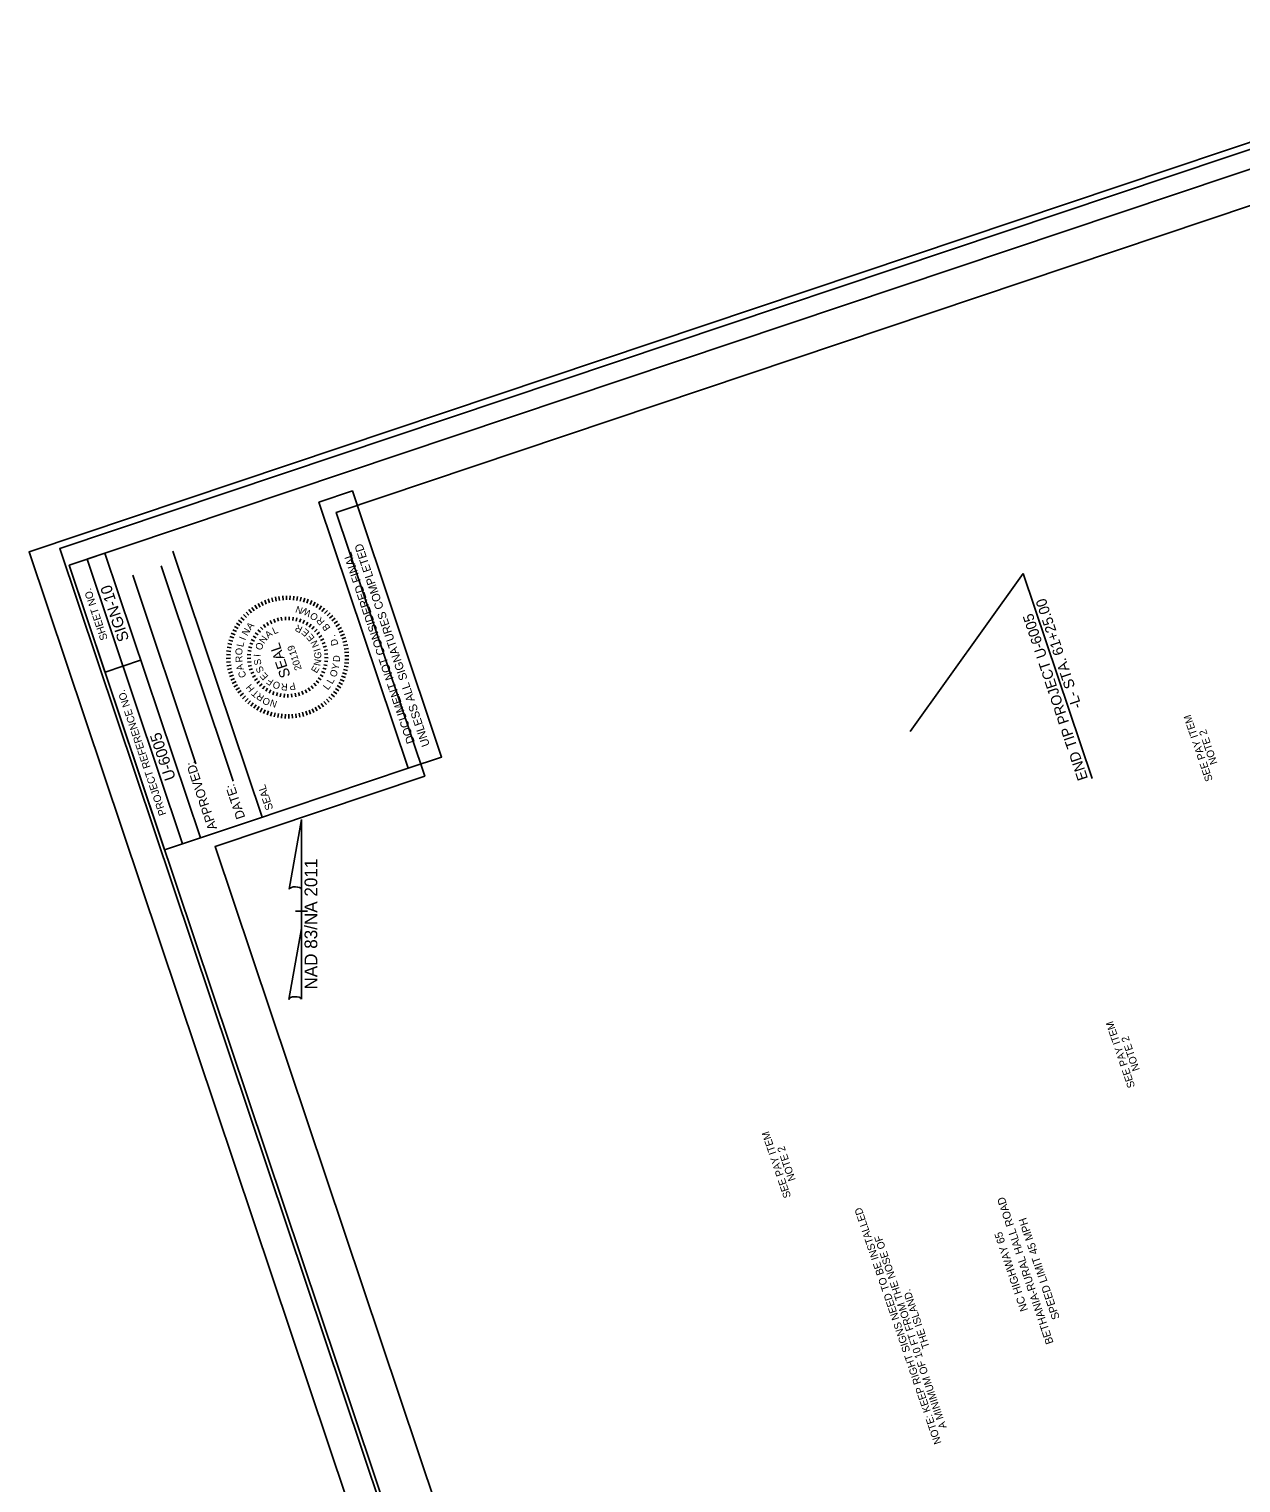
# Model space of a CAD drawing. Extents: x 1615436 to 1617010, y 903110 to 905055.
# Drawn here: x 1615436 to 1616244, y 904086 to 905055 of the extents above; entities that cross this region are included whole.
import ezdxf

# ---------------------------------------------------------------- set-up
doc = ezdxf.new("R2010")
doc.units = 0
for name, color, linetype in [('Default', 7, 'Continuous'), ('Exist DTM Regular Point Cogo Number', 7, 'Continuous'), ('Exist Structure Minor Pipes CMP 15 Inch Cogo Number', 7, 'Continuous'), ('Exist Structure Minor Pipes CMP 15 Inch Cogo Point CELL', 7, 'Continuous'), ('Exist Structure Minor Pipes RCP 15 Inch Cogo Number', 7, 'Continuous'), ('Exist Utilities Sanitary Sewer Manhole Cogo Number', 7, 'Continuous'), ('Prop RDY Traffic Signal CELL', 7, 'Continuous'), ('Sheet Layout Plan Border', 7, 'Continuous'), ('Sheet North Arrow Point CELL', 7, 'Continuous'), ('Sheet Plan CELL', 7, 'Continuous'), ('Sheet Plan Layout CELL', 7, 'Continuous'), ('Sheet Sticker Exception Certification CELL', 7, 'Continuous'), ('Sheet Sticker Preliminary CELL', 7, 'Continuous')]:
    doc.layers.add(name, color=color, linetype=linetype)

msp = doc.modelspace()

# ---------------------------------------------------------------- linework, layer by layer
at = {"layer": 'Default'}
for p, q in [((1615588.96, 904672.22), (1615590.31, 904669.78)), ((1615591.16, 904673.35), (1615592.35, 904670.83)), ((1615593.42, 904674.34), (1615594.46, 904671.76)), ((1615595.74, 904675.19), (1615596.62, 904672.55)), ((1615598.1, 904675.91), (1615598.83, 904673.22)), ((1615600.51, 904676.47), (1615601.07, 904673.75)), ((1615602.94, 904676.9), (1615603.33, 904674.14)), ((1615605.39, 904677.17), (1615605.62, 904674.39)), ((1615607.86, 904677.3), (1615607.92, 904674.51)), ((1615610.33, 904677.27), (1615610.21, 904674.49)), ((1615612.79, 904677.1), (1615612.51, 904674.33)), ((1615615.24, 904676.78), (1615614.79, 904674.03)), ((1615617.66, 904676.31), (1615617.05, 904673.59)), ((1615620.05, 904675.7), (1615619.28, 904673.02)), ((1615622.4, 904674.94), (1615621.47, 904672.31)), ((1615624.71, 904674.04), (1615623.61, 904671.48)), ((1615626.95, 904673), (1615625.7, 904670.51)), ((1615577.55, 904662.9), (1615579.68, 904661.09)), ((1615579.21, 904664.73), (1615581.22, 904662.8)), ((1615580.97, 904666.46), (1615582.86, 904664.41)), ((1615582.83, 904668.08), (1615584.6, 904665.92)), ((1615584.79, 904669.58), (1615586.42, 904667.32)), ((1615586.84, 904670.97), (1615588.32, 904668.61)), ((1615602.03, 904662.53), (1615602.61, 904660.28)), ((1615604.86, 904660.74), (1615604.49, 904663.04)), ((1615607.17, 904663.33), (1615607.3, 904661.01)), ((1615609.77, 904663.35), (1615609.68, 904661.03)), ((1615612.37, 904663.12), (1615612.05, 904660.82)), ((1615614.92, 904662.64), (1615614.39, 904660.38)), ((1615629.12, 904671.84), (1615627.73, 904669.42)), ((1615631.22, 904670.54), (1615629.69, 904668.22)), ((1615633.24, 904669.12), (1615631.57, 904666.89)), ((1615635.17, 904667.58), (1615633.37, 904665.45)), ((1615637, 904665.92), (1615635.07, 904663.91)), ((1615638.73, 904664.16), (1615636.68, 904662.27)), ((1615572.13, 904654.67), (1615574.62, 904653.43)), ((1615573.29, 904656.85), (1615575.7, 904655.46)), ((1615574.59, 904658.95), (1615576.91, 904657.41)), ((1615576.01, 904660.97), (1615578.24, 904659.3)), ((1615588.82, 904654.6), (1615590.53, 904653.04)), ((1615590.66, 904656.44), (1615592.22, 904654.72)), ((1615592.68, 904658.09), (1615594.06, 904656.22)), ((1615594.84, 904659.53), (1615596.04, 904657.54)), ((1615597.14, 904660.76), (1615598.13, 904658.67)), ((1615599.54, 904661.76), (1615600.33, 904659.58)), ((1615617.43, 904661.92), (1615616.68, 904659.72)), ((1615619.84, 904660.95), (1615618.89, 904658.84)), ((1615622.16, 904659.77), (1615621, 904657.75)), ((1615624.35, 904658.36), (1615623, 904656.47)), ((1615626.39, 904656.75), (1615624.87, 904654.99)), ((1615628.27, 904654.94), (1615626.58, 904653.35)), ((1615629.97, 904652.97), (1615628.13, 904651.54)), ((1615640.35, 904662.3), (1615638.19, 904660.53)), ((1615641.86, 904660.34), (1615639.59, 904658.71)), ((1615643.24, 904658.29), (1615640.88, 904656.8)), ((1615644.5, 904656.17), (1615642.06, 904654.82)), ((1615645.62, 904653.97), (1615643.11, 904652.78)), ((1615568.82, 904645.39), (1615571.54, 904644.78)), ((1615569.43, 904647.78), (1615572.11, 904647.01)), ((1615570.19, 904650.13), (1615572.81, 904649.2)), ((1615571.09, 904652.43), (1615573.65, 904651.34)), ((1615582.65, 904643.28), (1615584.9, 904642.69)), ((1615583.43, 904645.77), (1615585.61, 904644.96)), ((1615584.45, 904648.16), (1615586.54, 904647.15)), ((1615585.7, 904650.45), (1615587.68, 904649.24)), ((1615587.15, 904652.6), (1615589.02, 904651.21)), ((1615631.46, 904650.84), (1615629.5, 904649.59)), ((1615632.75, 904648.57), (1615630.68, 904647.53)), ((1615633.81, 904646.2), (1615631.64, 904645.36)), ((1615634.63, 904643.73), (1615632.4, 904643.1)), ((1615646.61, 904651.71), (1615644.03, 904650.67)), ((1615647.47, 904649.39), (1615644.82, 904648.51)), ((1615648.18, 904647.03), (1615645.49, 904646.3)), ((1615648.75, 904644.62), (1615646.02, 904644.06)), ((1615567.83, 904635.59), (1615570.62, 904635.65)), ((1615567.86, 904638.05), (1615570.64, 904637.94)), ((1615568.03, 904640.52), (1615570.8, 904640.24)), ((1615568.35, 904642.96), (1615571.1, 904642.52)), ((1615581.77, 904635.54), (1615584.1, 904635.62)), ((1615581.81, 904638.15), (1615584.13, 904638)), ((1615582.11, 904640.74), (1615584.4, 904640.37)), ((1615635.22, 904641.19), (1615632.93, 904640.78)), ((1615635.47, 904633.41), (1615633.16, 904633.67)), ((1615633.24, 904638.41), (1615635.56, 904638.59)), ((1615635.64, 904636.01), (1615633.31, 904636.05)), ((1615649.17, 904642.19), (1615646.41, 904641.8)), ((1615649.44, 904639.74), (1615646.67, 904639.51)), ((1615649.55, 904634.8), (1615646.76, 904634.92)), ((1615649.57, 904637.27), (1615646.78, 904637.21)), ((1615567.96, 904633.12), (1615570.74, 904633.35)), ((1615568.23, 904630.66), (1615570.99, 904631.06)), ((1615568.66, 904628.23), (1615571.38, 904628.79)), ((1615569.22, 904625.83), (1615571.91, 904626.55)), ((1615569.94, 904623.47), (1615572.58, 904624.35)), ((1615581.99, 904632.95), (1615584.29, 904633.25)), ((1615582.45, 904630.39), (1615584.71, 904630.91)), ((1615583.15, 904627.88), (1615585.35, 904628.62)), ((1615585.35, 904628.62), (1615583.15, 904627.88)), ((1615584.1, 904625.46), (1615586.22, 904626.4)), ((1615585.27, 904623.14), (1615587.29, 904624.28)), ((1615632.36, 904623.54), (1615630.32, 904624.65)), ((1615633.49, 904625.88), (1615631.35, 904626.79)), ((1615634.39, 904628.32), (1615632.18, 904629.02)), ((1615635.05, 904630.84), (1615632.78, 904631.32)), ((1615647.97, 904625.07), (1615645.29, 904625.85)), ((1615648.58, 904627.47), (1615645.86, 904628.08)), ((1615649.05, 904629.89), (1615646.3, 904630.34)), ((1615649.37, 904632.34), (1615646.6, 904632.62)), ((1615570.79, 904621.15), (1615573.37, 904622.19)), ((1615571.78, 904618.89), (1615574.3, 904620.08)), ((1615572.91, 904616.69), (1615575.35, 904618.03)), ((1615574.16, 904614.57), (1615576.52, 904616.05)), ((1615575.55, 904612.52), (1615577.81, 904614.15)), ((1615586.66, 904620.94), (1615588.56, 904622.27)), ((1615588.26, 904618.88), (1615590.02, 904620.39)), ((1615590.05, 904616.99), (1615591.66, 904618.66)), ((1615592.01, 904615.28), (1615593.45, 904617.1)), ((1615594.13, 904613.77), (1615595.39, 904615.72)), ((1615596.39, 904612.47), (1615597.45, 904614.54)), ((1615621.42, 904612.68), (1615620.33, 904614.73)), ((1615623.66, 904614.02), (1615622.37, 904615.95)), ((1615625.75, 904615.57), (1615624.28, 904617.37)), ((1615627.68, 904617.31), (1615626.05, 904618.96)), ((1615629.44, 904619.23), (1615627.65, 904620.72)), ((1615631.01, 904621.31), (1615629.08, 904622.62)), ((1615642.81, 904613.91), (1615640.49, 904615.44)), ((1615644.11, 904616.01), (1615641.7, 904617.4)), ((1615645.28, 904618.18), (1615642.79, 904619.43)), ((1615646.31, 904620.42), (1615643.75, 904621.52)), ((1615647.21, 904622.73), (1615644.59, 904623.66)), ((1615577.05, 904610.56), (1615579.21, 904612.33)), ((1615578.67, 904608.7), (1615580.72, 904610.59)), ((1615580.4, 904606.93), (1615582.33, 904608.95)), ((1615582.23, 904605.28), (1615584.04, 904607.4)), ((1615584.16, 904603.74), (1615585.83, 904605.97)), ((1615586.18, 904602.32), (1615587.71, 904604.64)), ((1615598.76, 904611.39), (1615599.61, 904613.55)), ((1615601.22, 904610.55), (1615601.87, 904612.78)), ((1615603.75, 904609.95), (1615604.18, 904612.23)), ((1615606.33, 904609.59), (1615606.54, 904611.91)), ((1615608.93, 904609.49), (1615608.91, 904611.81)), ((1615611.53, 904609.64), (1615611.29, 904611.95)), ((1615614.1, 904610.04), (1615613.64, 904612.31)), ((1615616.63, 904610.68), (1615615.95, 904612.9)), ((1615619.07, 904611.56), (1615618.18, 904613.71)), ((1615632.61, 904603.27), (1615630.98, 904605.54)), ((1615634.57, 904604.78), (1615632.8, 904606.94)), ((1615636.43, 904606.4), (1615634.54, 904608.45)), ((1615638.2, 904608.13), (1615636.18, 904610.06)), ((1615639.85, 904609.96), (1615637.73, 904611.76)), ((1615641.39, 904611.89), (1615639.16, 904613.56)), ((1615588.28, 904601.02), (1615589.67, 904603.43)), ((1615590.46, 904599.85), (1615591.7, 904602.34)), ((1615592.7, 904598.82), (1615593.79, 904601.38)), ((1615595, 904597.92), (1615595.93, 904600.54)), ((1615597.35, 904597.16), (1615598.12, 904599.84)), ((1615599.74, 904596.55), (1615600.35, 904599.26)), ((1615602.17, 904596.08), (1615602.61, 904598.83)), ((1615604.61, 904595.76), (1615604.89, 904598.53)), ((1615607.08, 904595.58), (1615607.19, 904598.37)), ((1615609.54, 904595.56), (1615609.48, 904598.35)), ((1615612.01, 904595.69), (1615611.78, 904598.46)), ((1615614.47, 904595.96), (1615614.07, 904598.72)), ((1615616.9, 904596.38), (1615616.34, 904599.11)), ((1615619.3, 904596.95), (1615618.58, 904599.64)), ((1615621.66, 904597.66), (1615620.78, 904600.31)), ((1615623.98, 904598.52), (1615622.94, 904601.1)), ((1615626.24, 904599.51), (1615625.05, 904602.02)), ((1615628.44, 904600.63), (1615627.1, 904603.07)), ((1615630.56, 904601.89), (1615629.08, 904604.25))]:
    msp.add_line(p, q, dxfattribs=at)
at = {"layer": 'Exist DTM Regular Point Cogo Number'}
msp.add_lwpolyline([(1616672.58, 903656.2), (1616919.77, 903656.8), (1616590.65, 904611.24), (1616386.84, 904624.44), (1616334.81, 904821.64), (1616466, 905009.57), (1615641.09, 904732.87), (1615700.02, 904557.19), (1615560.35, 904510.33), (1615954.19, 903336.21)], close=True, dxfattribs=at)
at = {"layer": 'Exist Structure Minor Pipes CMP 15 Inch Cogo Point CELL'}
for p, q in [((1615572.45, 904553.86), (1615524.33, 904697.3)), ((1615547.63, 904565.24), (1615505.46, 904690.97))]:
    msp.add_line(p, q, dxfattribs=at)
at = {"layer": 'Exist Structure Minor Pipes RCP 15 Inch Cogo Number'}
for p, q in [((1615538.66, 904511.93), (1615475.05, 904701.6)), ((1615550.54, 904515.93), (1615486.9, 904705.57)), ((1615550.54, 904515.93), (1615486.9, 904705.57)), ((1615487.07, 904626.5), (1615510.76, 904634.49))]:
    msp.add_line(p, q, dxfattribs=at)
for points in [[(1615463.14, 904697.64), (1615940.18, 903275.48), (1616935.67, 903609.4), (1616458.64, 905031.54)], [(1615526.76, 904507.95), (1615463.14, 904697.64), (1615486.9, 904705.57), (1615550.54, 904515.93)]]:
    msp.add_lwpolyline(points, close=True, dxfattribs=at)
at = {"layer": 'Exist Utilities Sanitary Sewer Manhole Cogo Number'}
for p, q in [((1615629.54, 904739.64), (1615689.01, 904562.36)), ((1615591.68, 904529.71), (1615532.21, 904706.99)), ((1615689.01, 904562.36), (1615583.39, 904526.93)), ((1615583.39, 904526.93), (1615538.66, 904511.93))]:
    msp.add_line(p, q, dxfattribs=at)
at = {"layer": 'Prop RDY Traffic Signal CELL'}
msp.add_line((1615617.56, 904466.62), (1615617.56, 904466.62), dxfattribs=at)
at = {"layer": 'Sheet Layout Plan Border'}
msp.add_lwpolyline([(1616986.86, 903464.68), (1616457.04, 905044.17), (1615456.82, 904708.68), (1615986.63, 903129.17)], close=True, dxfattribs=at)
at = {"layer": 'Sheet Plan CELL'}
msp.add_lwpolyline([(1615689.01, 904562.36), (1615629.54, 904739.64), (1615651.81, 904747.11), (1615711.28, 904569.83)], close=True, dxfattribs=at)
at = {"layer": 'Sheet Plan Layout CELL'}
for p, q in [((1616023.42, 904586.81), (1616098.85, 904692.18)), ((1616098.85, 904692.18), (1616144.69, 904555.5))]:
    msp.add_line(p, q, dxfattribs=at)
at = {"layer": 'Sheet Sticker Exception Certification CELL'}
msp.add_lwpolyline([(1617009.96, 903458.71), (1616474.57, 905054.81), (1615436.42, 904706.58), (1615971.81, 903110.48)], close=True, dxfattribs=at)
at = {"layer": 'Sheet Sticker Preliminary CELL'}
for p, q in [((1615609.69, 904481.91), (1615617.89, 904528.26)), ((1615617.94, 904528.26), (1615617.89, 904528.26)), ((1615617.94, 904528.26), (1615617.89, 904528.26)), ((1615617.94, 904528.26), (1615617.94, 904480.46)), ((1615617.94, 904455.66), (1615617.94, 904481.86)), ((1615617.94, 904480.46), (1615617.94, 904481.81)), ((1615613.94, 904467.26), (1615613.89, 904467.26)), ((1615617.49, 904467.26), (1615613.94, 904467.26)), ((1615613.99, 904467.26), (1615621.99, 904467.26)), ((1615617.94, 904455.66), (1615609.59, 904408.41)), ((1615617.99, 904408.61), (1615617.94, 904455.66))]:
    msp.add_line(p, q, dxfattribs=at)
for centre, start_param, end_param in [((1615613.83, 904481.42), 0.216388, 2.908219), ((1615613.83, 904408.25), 0.201328, 3.141593)]:
    msp.add_ellipse(centre, major_axis=(4.23, -0.03), ratio=0.461098, start_param=start_param, end_param=end_param, dxfattribs=at)

# ---------------------------------------------------------------- texts
at = {"layer": 'Default'}
for s, height, rotation, p in [('N', 4.64, 160.69721, (1615619.21, 904669.21)), ('W', 4.64, 151.81458, (1615624.87, 904667)), ('O', 4.64, 142.93195, (1615629.62, 904663.78)), ('R', 4.64, 134.10934, (1615633.71, 904660.29)), ('N', 4.64, 58.77478, (1615581.78, 904650.16)), ('A', 4.64, 49.00725, (1615584.06, 904654.15)), ('A', 4.64, 39.65705, (1615595.87, 904648.59)), ('L', 4.64, 24.3608, (1615599.75, 904651.47)), ('R', 4.64, 153.05505, (1615619.11, 904656.3)), ('E', 4.64, 139.28396, (1615623.58, 904653.13)), ('B', 4.64, 125.10677, (1615637.41, 904655.87)), ('L', 4.64, 77.64472, (1615579.08, 904642.85)), ('I', 4.64, 68.06925, (1615580.44, 904647.26)), ('O', 4.64, 70.24954, (1615591.26, 904640.59)), ('N', 4.64, 54.9533, (1615593.08, 904644.97)), ('SEAL', 6.965, 108.49016, (1615610.68, 904623.93)), ('20119', 4.64, 108.49016, (1615618.17, 904628.44)), ('E', 4.64, 129.29808, (1615626.96, 904649.24)), ('N', 4.64, 113.90601, (1615629.81, 904644)), ('D', 4.64, 104.58011, (1615642.54, 904644.64)), ('.', 4.64, 112.32246, (1615640.72, 904650.2)), ('O', 4.64, 90.781, (1615578.61, 904637.72)), ('R', 4.64, 93.83781, (1615578.77, 904633.04)), ('I', 4.64, 85.54579, (1615590.73, 904636.47)), ('S', 4.64, 100.84203, (1615591.35, 904631.47)), ('I', 4.64, 106.27635, (1615630.66, 904640.96)), ('N', 4.64, 79.41532, (1615630.38, 904630.25)), ('G', 4.64, 88.18155, (1615631.01, 904635.25)), ('D', 4.64, 86.7848, (1615643.44, 904633.05)), ('A', 4.64, 105.84712, (1615579.68, 904628.16)), ('C', 4.64, 105.84712, (1615581.2, 904623.32)), ('S', 4.64, 116.13828, (1615593.18, 904627.2)), ('E', 4.64, 131.43453, (1615596.08, 904623.58)), ('E', 4.64, 58.56025, (1615627.95, 904625.33)), ('O', 4.64, 69.13974, (1615640.76, 904622.6)), ('Y', 4.64, 77.81232, (1615642.48, 904627.63)), ('H', 4.64, 129.55781, (1615586.96, 904615.51)), ('T', 4.64, 138.98976, (1615590.06, 904612.6)), ('F', 4.64, 146.73077, (1615599.74, 904620.89)), ('O', 4.64, 162.02702, (1615604.27, 904619.15)), ('R', 4.64, 177.32326, (1615608.81, 904618.73)), ('P', 4.64, 192.61951, (1615613.39, 904619.52)), ('L', 4.64, 52.42517, (1615635.54, 904614.11)), ('L', 4.64, 60.49699, (1615638.41, 904618.1)), ('R', 4.64, 147.15072, (1615593.51, 904610.47)), ('O', 4.64, 160.20745, (1615597.54, 904608.27)), ('N', 4.64, 162.16688, (1615602.1, 904606.99)), ('SEE PAY ITEM', 5, 108.77928, (1616225.2, 904554.52)), ('NOTE 2', 5, 108.77928, (1616228.3, 904565.78)), ('SEE PAY ITEM', 5, 108.77928, (1616173.41, 904350.35)), ('NOTE 2', 5, 108.77928, (1616176.51, 904361.61)), ('SEE PAY ITEM', 5, 108.77928, (1615944.17, 904277.03)), ('NOTE 2', 5, 108.77928, (1615947.26, 904288.29)), ('BETHANIA-RURAL HALL ROAD ', 5.25, 108.60948, (1616119.1, 904179.67)), ('NOTE: KEEP RIGHT SIGNS NEED TO BE INSTALLED ', 5, 108.77928, (1616044.41, 904112.99)), ('SPEED LIMIT 45 MPH', 5.25, 108.60948, (1616123.25, 904196.13)), ('A MINIMUM OF 10 FT FROM THE NOSE OF', 5, 108.77928, (1616047.82, 904123.32)), ('NC HIGHWAY 65', 5.25, 108.60948, (1616102.06, 904201.52)), ('THE ISLAND.', 5, 108.77928, (1616036.57, 904176.76))]:
    msp.add_text(s, height=height, rotation=rotation, dxfattribs=at).set_placement(p)
at = {"layer": 'Exist Structure Minor Pipes CMP 15 Inch Cogo Number'}
for s, p in [('APPROVED:', (1615561.72, 904522.39)), ('DATE:', (1615580.52, 904529.67))]:
    msp.add_text(s, height=6.11, rotation=108.53811, dxfattribs=at).set_placement(p)
at = {"layer": 'Exist Structure Minor Pipes CMP 15 Inch Cogo Point CELL'}
msp.add_text('SEAL', height=5.094, rotation=108.53811, dxfattribs=at).set_placement((1615599.16, 904535.41))
at = {"layer": 'Exist Structure Minor Pipes RCP 15 Inch Cogo Number'}
for s, height, p in [('SHEET NO.', 5, (1615488.91, 904648.58)), ('PROJECT REFERENCE NO.', 5.0001, (1615527.97, 904531.77))]:
    msp.add_text(s, height=height, rotation=108.54318, dxfattribs=at).set_placement(p)
at = {"layer": 'Sheet North Arrow Point CELL'}
for s, p in [('SIGN-10', (1615503.21, 904648.16)), ('U-6005', (1615534.29, 904555.69))]:
    msp.add_text(s, height=7.5, rotation=108.54318, dxfattribs=at).set_placement(p)
at = {"layer": 'Sheet Plan CELL'}
for s, p in [('UNLESS ALL SIGNATURES COMPLETED', (1615703.5, 904577.78)), ('DOCUMENT NOT CONSIDERED FINAL', (1615693.55, 904579.79))]:
    msp.add_text(s, height=5.4984, rotation=108.54317, dxfattribs=at).set_placement(p)
at = {"layer": 'Sheet Plan Layout CELL'}
for s, p in [('-L- STA. 61+25.00', (1616137.98, 904603.38)), ('END TIP PROJECT U-6005', (1616142.01, 904555.6))]:
    msp.add_text(s, height=7, rotation=108.54317, dxfattribs=at).set_placement(p)
at = {"layer": 'Sheet Sticker Preliminary CELL'}
msp.add_text('NAD 83/NA 2011', height=8.5, rotation=90, dxfattribs=at).set_placement((1615628.46, 904414.96))

doc.saveas('drawing.dxf')
